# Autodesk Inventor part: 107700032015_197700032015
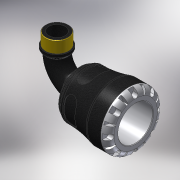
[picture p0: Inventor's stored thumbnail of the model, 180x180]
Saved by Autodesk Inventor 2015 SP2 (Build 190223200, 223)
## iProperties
Created: 2016-12
Part Number: 107700032015_197700032015
Material: PVC-Piping
Description: PLASSON 90° ELBOW WITH MALE INTEGRAL BRASS 32X1.1/2" SERIES 1
Document SubType Name: Modeling
Designer: KIM
Mass: 664.223 g
Surface Area: 733.008 cm^2
Volume: 474.445 cm^3
Density: 1.4 g/cm^3
Appearance: Black Cast
Author: KIM
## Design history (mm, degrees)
derived "1077.ipt"
feature "Solid1::1077.ipt"
tag "TaggingFeature1"
body "Solid1"
other parameters: "d1" = 22.68, "d2" = 32, "d4" = 58, "d8" = 49.3, "d13" = 7.2, "d14" = 7.2, "d15" = 0, "d17" = 360 deg, "d19" = 8 deg, "d20" = 0.64, "d21" = 0.64, "d22" = 8 deg, "d24" = 0, "d26" = 360 deg, "d33" = 5.8, "d43" = 45.24, "d51" = 0.58, "d54" = 11.2, "d55" = 7.04, "d57" = 14.112, "d58" = 0, "d74" = 0, "d78" = 54, "d82" = 0.64, "d115" = 360 deg, "d207" = 90 deg, "d228" = 9.52, "d247" = 1.16, "d248" = 3.24, "d268" = 27.115, "d269" = 3.24, "d270" = 81, "d276" = 47.803, "d278" = 52.5833, "d279" = 83, "d280" = 26, "d281" = 7.17045, "d283" = 43.0227, "d286" = 0, "d287" = 0, "d288" = 33.4621, "d290" = 1.10865, "d292" = 30 deg, "d294" = 4.7803, "d296" = 30 deg, "d_" = 32, "E_" = 58, "l_" = 54, "A_" = 81, "A_1" = 83, "R_" = 47.803, "d9" = 9, "d11" = 58, "d289" = 33.4621
